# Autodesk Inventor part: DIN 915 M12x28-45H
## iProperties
Shininess: 64.0
Length Units: 11269
Angle Units: 11279
Time Units: 11290
Mass Units: 11283
Length Display Precision: 3
Angle Display Precision: 2
Compacted: True
Part Number: DIN 915 M12x28-45H
Document SubType Name: Modeling
Created: 2005-02
Material: Par défaut
Designer: LEGERET Philippe
Catalog Web Link: www.traceparts.com
Description: Vis à métaux - Sans tête à téton DIN 915 M12x28-45H
Density: 0.0
Volumn: 0.0
Area: 0.0
PropertySet Name: Model Information
Control State: 0
Master: False
Checked Out: False
Author: Trace Parts S.A.
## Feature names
1. Base1
